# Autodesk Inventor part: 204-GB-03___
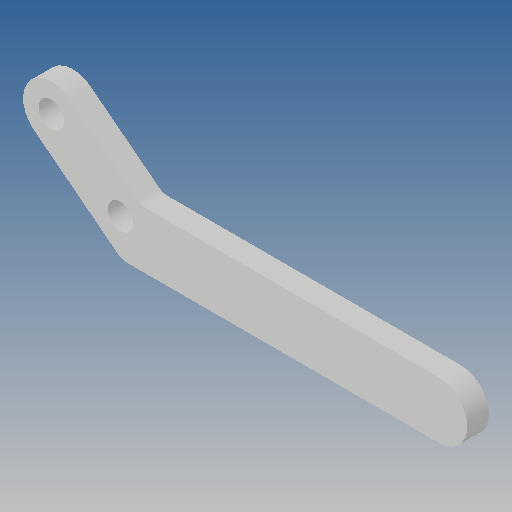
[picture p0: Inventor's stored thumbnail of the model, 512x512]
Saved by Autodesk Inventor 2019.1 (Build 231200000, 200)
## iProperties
Created: 2010-06
Part Number: 204-GB-03___
Material: Ogólny
Document SubType Name: Modeling
Designer: CADENGINEERING4
Density: 1 g/cm^3
Appearance: Domyślna
Author: CADENGINEERING4
Revision Number: ANY
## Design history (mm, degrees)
feature "NONE"
node "Bryła1"
